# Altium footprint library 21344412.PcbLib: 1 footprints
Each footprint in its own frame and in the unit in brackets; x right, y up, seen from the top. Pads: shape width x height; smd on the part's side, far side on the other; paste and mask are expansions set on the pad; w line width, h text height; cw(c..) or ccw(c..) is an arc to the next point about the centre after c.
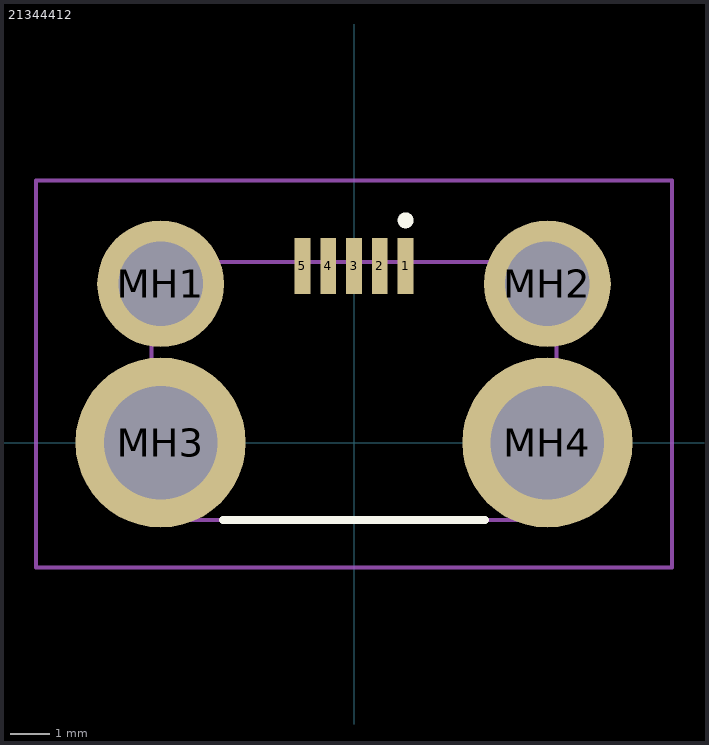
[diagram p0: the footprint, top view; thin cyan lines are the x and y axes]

## 21344412 [mm]
pads (9):
  rect 0.4x1.4 smd: 1(1.3,4.45) 2(0.65,4.45) 3(0,4.45) 4(-0.65,4.45) 5(-1.3,4.45)
  round 3.195 hole 2.13: MH1(-4.875,4) MH2(4.875,4)
  round 4.29 hole 2.86: MH3(-4.875,0) MH4(4.875,0)
Top Overlay:
  lines w0.2: -3.3,-1.95 3.3,-1.95 ; 1.3,5.5 1.3,5.5 ; 1.3,5.5 ccw(c1.3,5.6) 1.3,5.7 ; 1.3,5.5 cw(c1.3,5.6) 1.3,5.7 ; 1.3,5.7 1.3,5.7
Mechanical 15:
  lines w0.1: -5.1,-1.95 5.1,-1.95 5.1,4.55 -5.1,4.55 -5.1,-1.95
Mechanical 20:
  lines w0.1: -8.02,-3.145 8.02,-3.145 8.02,6.6 -8.02,6.6 -8.02,-3.145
